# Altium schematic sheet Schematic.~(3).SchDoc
size A4; SheetNumber: 1; SheetTotal: 1
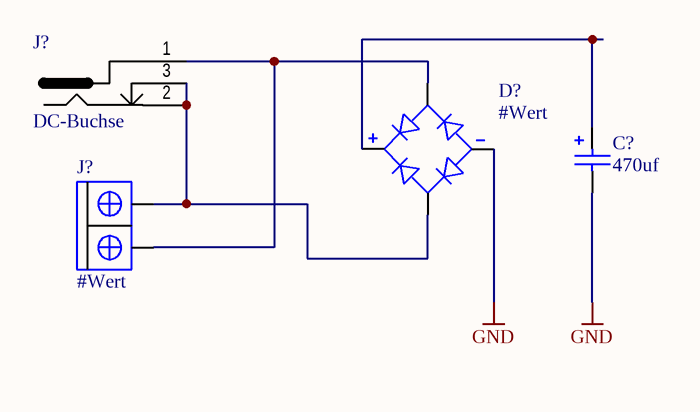
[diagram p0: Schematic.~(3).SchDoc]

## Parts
(Parts that share a designator on the sheet are numbered #1, #2 ... from top to bottom, then left to right.)
C?  470uf  [C_SMD_D-TYP]
D?  #Wert  [D_THT_FBR-R]
J?#1  DC-Buchse  [J_THT_CJ-25]
J?#2  #Wert  [J_THT_Printklemme 2x]

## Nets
GND: C?.2 D?.4(NEG)
NetC?_1: C?.1 D?.1(POS)
NetD?_2: D?.2(AC1) J?#1.1 J?#2.1
NetD?_3: D?.3(AC2) J?#1.2 J?#1.3 J?#2.2

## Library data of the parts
C? = C_SMD_ELK: SMD Elektrolytkondensator
D? = D_THT_Brückengleichrichter: Bruckengleichrichter
J?#1 = J_THT_Hohlstecker
J?#2 = J_THT_Printklemme 2x: Printklemme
